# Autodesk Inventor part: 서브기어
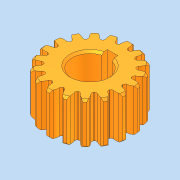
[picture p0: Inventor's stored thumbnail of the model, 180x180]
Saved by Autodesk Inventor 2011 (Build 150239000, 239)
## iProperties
Company: 한국ATC센터
Created: 2014-12
Part Number: 서브기어
Document SubType Name: Modeling
Designer: KYOUNG IL JANG
Density: 1 g/cm^3
Mass: 15.166 g
Surface Area: 69.6172 cm^2
Volume: 15.166 cm^3
Author: KYOUNG IL JANG
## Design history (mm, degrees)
sketch "스케치1"
  geometry: C1 r 15.5 at (0, 0); A1 r 1.155 centre (-2.906, 16.386) between (-2.542, 15.29) and (-1.751, 16.378); A2 r 5.602 centre (3.849, 16.522) between (-1.326, 18.666) and (-1.751, 16.378); A3 r 9.354 centre (7.378, 15.24) between (-0.682, 19.988) and (-1.326, 18.666); A4 r 1.155 centre (2.906, 16.386) between (1.751, 16.378) and (2.542, 15.29); A5 r 5.602 centre (-3.849, 16.522) between (1.751, 16.378) and (1.326, 18.666); A6 r 9.354 centre (-7.378, 15.24) between (1.326, 18.666) and (0.682, 19.988); A7 r 20 centre (0, 0) between (0.682, 19.988) and (-0.682, 19.988); A8 r 15.5 centre (0, 0) between (2.542, 15.29) and (-2.542, 15.29); 1 further point
  constraints: 16 point on circle, 9 centre point, 2 coincident
extrude "돌출1" new body sketch "스케치1" stored distance "d0" = 20; taper "d1" = 0 deg
extrude "돌출2" join sketch "스케치1" stored distance "d2" = 20; taper "d3" = 0 deg
chamfer "모따기1" distance "d4" = 1; stored, may be unused: second distance "d5" = 2, angle "d6" = 45 deg
hole "구멍1" diameter "d12" = 17; stored, may be unused: countersink angle "d16" = 90 deg, drill point angle "d18" = 118 deg; dims "d10" = 10, "d11" = 10, "d13" = 6, "d14" = 4, "d15" = 2, "d17" = 8
sketch "스케치2"
  geometry: L1 (-2.5, 8.124)-(-2.5, 10.8); L2 (-2.5, 10.8)-(2.5, 10.8); L3 (2.5, 10.8)-(2.5, 8.124); A1 r 8.5 centre (0, 0) between (-2.5, 8.124) and (2.5, 8.124) reference; 1 further point
  constraints: 6 end point, 2 parallel, 2 point on circle, 1 horizontal, 1 vertical
  dimensions: "d22" = 5 distance of L1.end L2.end; "d23" = 2.3 distance edge to line of A1 L2
extrude "돌출3" cut sketch "스케치2" stored distance "d24" = 20; taper "d25" = 0 deg
chamfer "모따기2" distance "d19" = 1; stored, may be unused: second distance "d20" = 2, angle "d21" = 45 deg
node "솔리드1"
pattern_circular "원형 패턴1" dims angle "d8" = 360 deg
